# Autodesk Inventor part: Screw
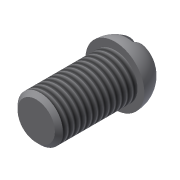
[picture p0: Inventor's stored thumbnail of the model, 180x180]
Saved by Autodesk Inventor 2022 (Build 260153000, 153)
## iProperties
Created: 2002-01
Part Number: Screw
Document SubType Name: Modeling
Designer: ***
Density: 1 g/cm^3
Material: Generic
Appearance: Default
Control State: 0
Master: False
Checked Out: False
Shininess: 77.0
Length Units: 11269
Angle Units: 11279
Time Units: 11290
Mass Units: 11283
Length Display Precision: 3
Angle Display Precision: 2
Density: 0.0
Volumn: 0.0
Area: 0.0
PropertySet Name: Model Information
Author: ***
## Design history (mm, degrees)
sketch "Sketch1"
  geometry: L1 (-0.061, 13.328)-(-0.061, -1.672); L2 (-0.061, -1.672)-(14.939, -1.672); A1 r 15 centre (-0.061, -1.672) between (14.939, -1.672) and (-0.061, 13.328)
  constraints: 4 end point, 2 point on circle, 1 centre point
  dimensions: "d0" = 15 radius of A1
revolve "Revolution1" sketch "Sketch1" stored, may be unused: angle "d3" = 90 deg
workplane "Work Plane2"
sketch "Sketch3"
  geometry: L1 (-3, 26)-(3, 26); L2 (3, 26)-(3, 6); L3 (3, 6)-(-3, 6); L4 (-3, 6)-(-3, 26); L5 (-15, 0)-(15, 0) reference
  constraints: 8 end point, 2 parallel, 1 horizontal, 1 perpendicular
  dimensions: "d11" = 6 distance of L1.start L1.end; "d12" = 20 distance of L3.end L1.start; "d13" = 6 distance between parallel lines of L5 L3; "d14" = 12 distance from line of L4 L5.start
extrude "Extrusion2" cut sketch "Sketch3" extent not by distance; stored distance "d15" = 10; taper "d16" = 0 deg
sketch "Sketch4"
  geometry: C1 r 11.5 at (0, 0); C2 r 15 at (0, 0) reference
  constraints: 1 centre point, 1 concentric
  dimensions: "d17" = 23 diameter of C1
extrude "Extrusion3" join sketch "Sketch4" distance "d18" = 40; taper "d19" = 0 deg
chamfer "Chamfer1" distance "d20" = 2; stored, may be unused: second distance "d21" = 2, angle "d24" = 45 deg
thread "Thread1" dims "d22" = 10, "d23" = 0
body "Solid1"
